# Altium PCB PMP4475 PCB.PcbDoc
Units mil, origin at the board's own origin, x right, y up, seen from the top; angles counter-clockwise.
Board outline 6000 x 4000 mil, 2 copper layers (Top Layer, Bottom Layer); 67 components, 35 nets, 172 pads, 89 vias.
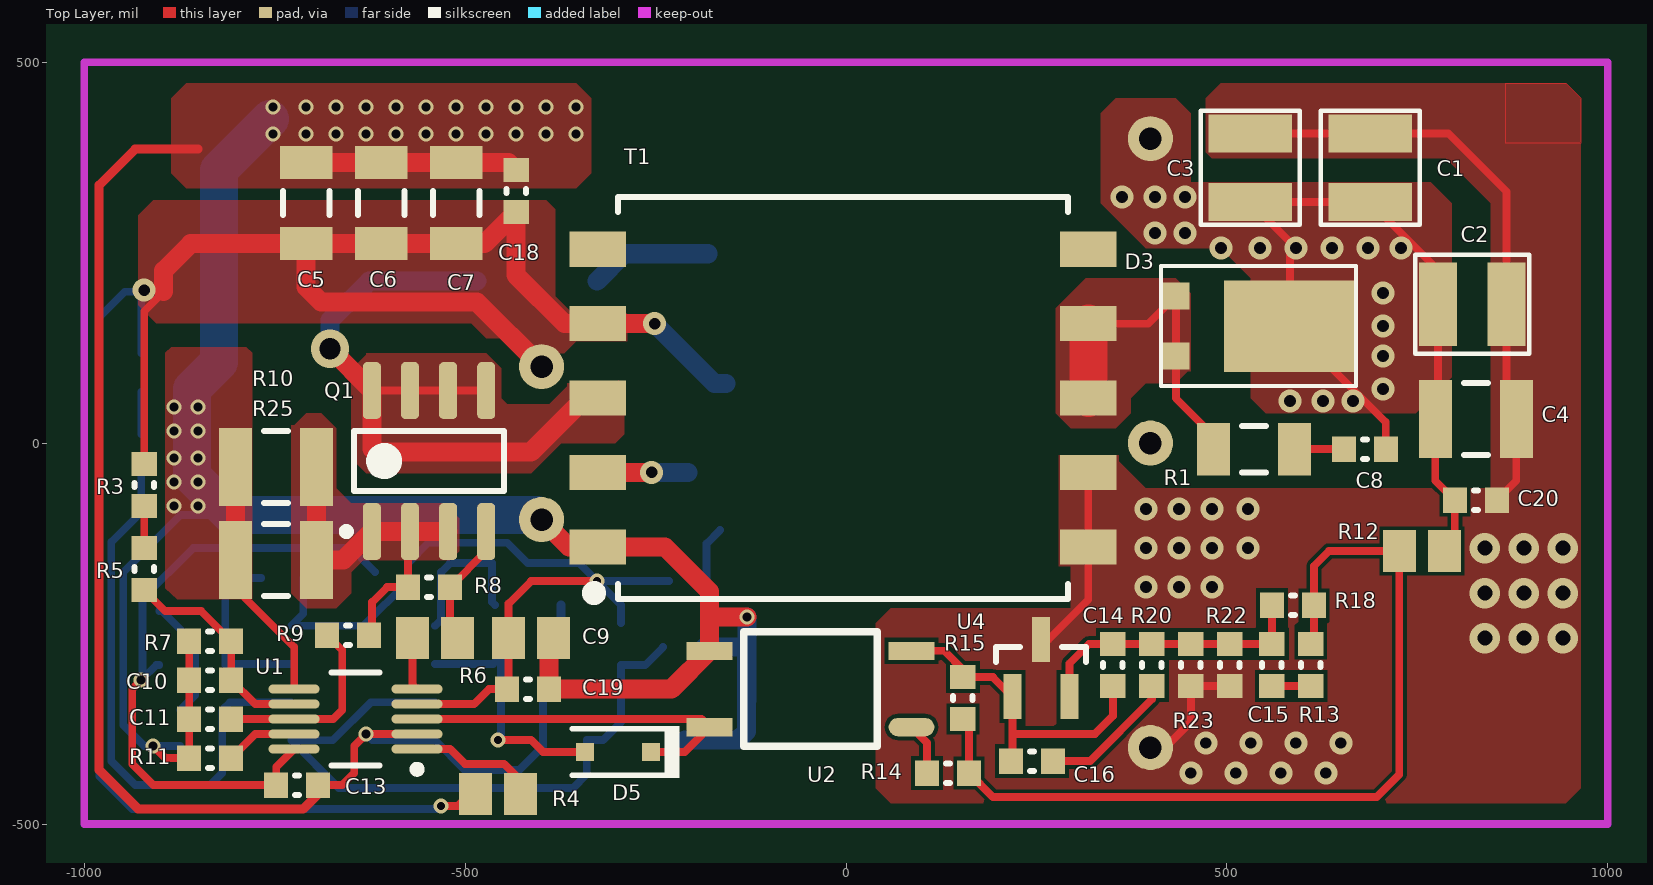
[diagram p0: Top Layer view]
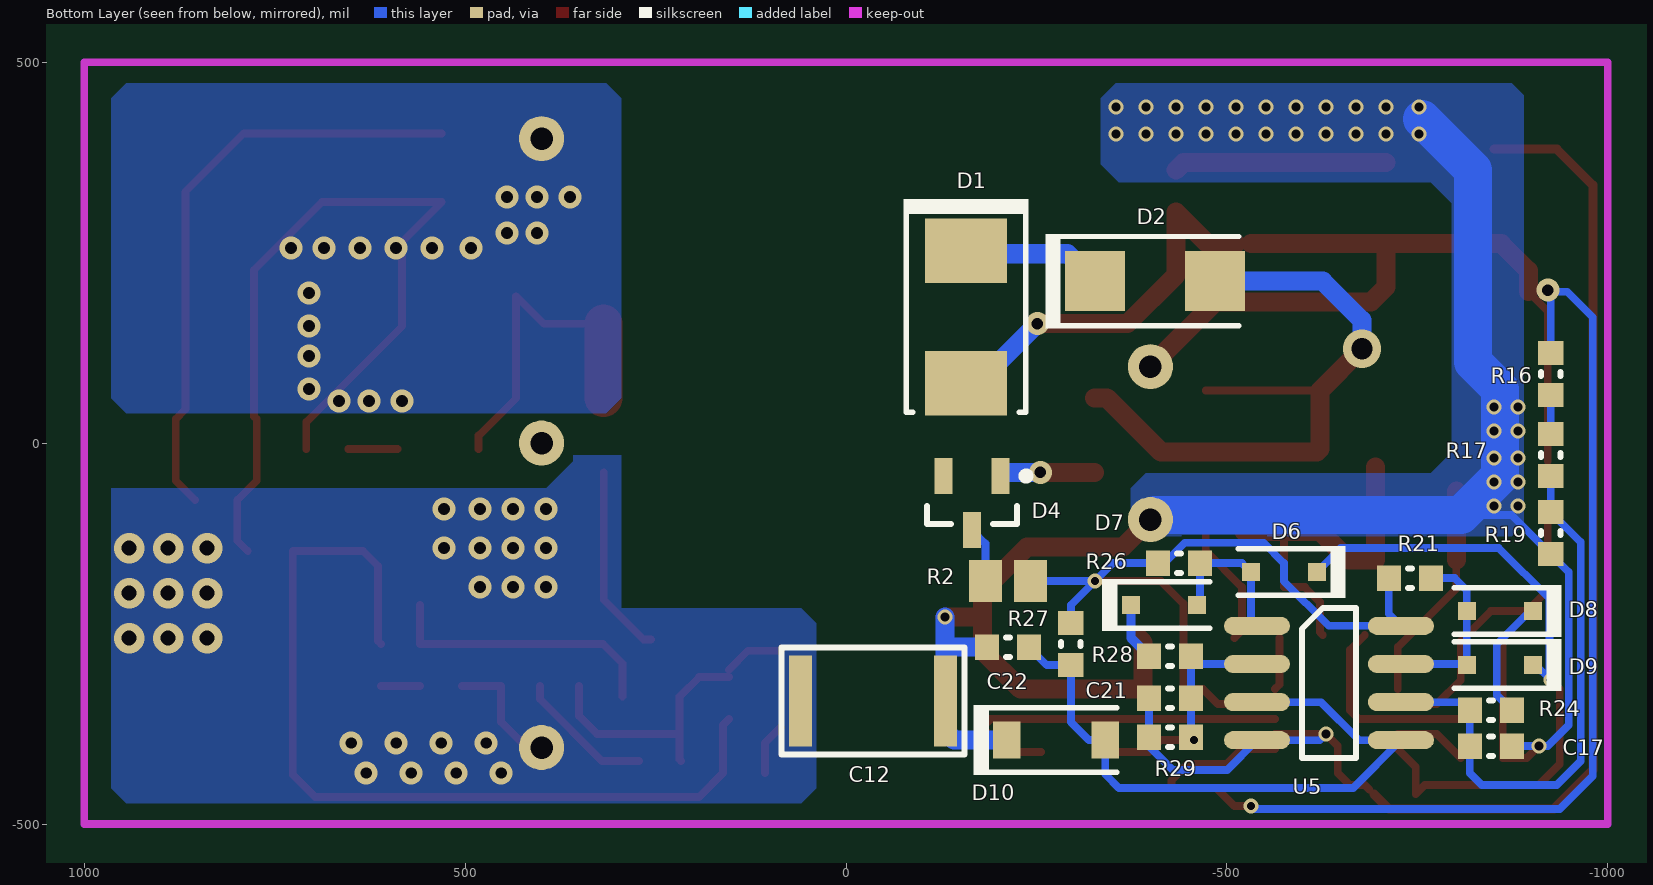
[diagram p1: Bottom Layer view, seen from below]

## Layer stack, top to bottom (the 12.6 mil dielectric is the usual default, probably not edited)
Top Layer: signal copper 1.4
Dielectric: dielectric 12.6, FR-4, Dk 4.8
Bottom Layer: signal copper 1.4

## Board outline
-2900,-2325 3100,-2325 3100,1675 -2900,1675

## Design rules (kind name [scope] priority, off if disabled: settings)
Clearance [All] p1: gap=5
MinimumSolderMaskSliver [All] p1: minsoldermaskwidth=0
PolygonConnect [All] p1: connectstyle=Direct reliefconductorwidth=10 reliefentries=4 polygonreliefangle="90 Angle" airgapwidth=10
RoutingVias [All] p1: holewidth=20 width=40 viastyle="Through Hole" minholewidth=10 minwidth=20 maxholewidth=30 maxwidth=60
SilkToSilkClearance [All] p1: silktosilkclearance=1
SilkscreenOverComponentPads [All] p1: minsilkscreentomaskgap=0
SolderMaskExpansion [All] p1: expansion=4
Width [All] p1: maxlimit=50 minlimit=10 preferedwidth=10
25 further rules are at their usual default settings.

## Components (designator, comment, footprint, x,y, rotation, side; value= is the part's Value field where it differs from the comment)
C1 "6TPE150MAPB" "POSCAP B2E Size" 748.03,291.34 r90 top
C2 "6TPE150MAPB" "POSCAP B2E Size" 751.97,122.05 r0 top
C3 "6TPE150MAPB" "POSCAP B2E Size" 590.55,291.34 r90 top
C4 "GRM32ER61A476KE20L" 1210L 826.77,31.5 r0 top
C5 "GRM31CR71H475KA12L" 1206L -708.66,314.96 r90 top
C6 "GRM31CR71H475KA12L" 1206L -610.24,314.96 r90 top
C7 "GRM31CR71H475KA12L" 1206L -511.81,314.96 r90 top
C8 "GRM1885C1H102JA01D" 0603L 681.1,-7.87 r180 top
C9 "GRM21BR71E335KA73L" 0805L -413.39,-255.91 r0 top
C10 "GRM188R71E474KA12D" 0603L -834.65,-311.02 r180 top
C11 "C0603C101J5GAC" 0603L -834.65,-362.2 r180 top
C12 "GRM1885C1H102JA01D" 2211 -35.43,-338.58 r180 bottom
C13 "GRM188R71C104KA01D" 0603L -720.47,-448.82 r0 top
C14 "GRM1885C1H102JA01D" 0603L 350.39,-291.34 r270 top
C15 "GRM188R71E474KA12D" 0603L 559.06,-291.34 r270 top
C16 "GRM188R71E474KA12D" 0603L 244.09,-417.32 r0 top
C17 "GRM188R71C104KA01D" 0603L -846.46,-397.64 r180 bottom
C18 "GRM188R71C104KA01D" 0603L -433.07,330.71 r90 top
C19 "GRM188R71C104KA01D" 0603L -417.32,-322.83 r0 top
C20 "GRM188R71C104KA01D" 0603L 826.77,-74.8 r0 top
C21 "GRM188R71C104KA01D" 0603L -425.2,-334.65 r0 bottom
C22 "GRM188R71C104KA01D" 0603L -212.6,-267.72 r0 bottom
D1 "SMBJ36A-13-F" SMB -157.48,165.35 r270 bottom
D2 "MURA160T3G" SMA -405.51,212.6 r180 bottom
D3 "PDS1040L" POWERDI-5 669.29,232.28 r180 top
D4 "BAS16-7-F" SOT-23L -165.35,-78.74 r270 bottom
D5 "BAS16" SOD-323F -299.21,-405.51 r180 top
D6 "BAS16" SOD-323F -574.8,-169.29 r0 bottom
D7 "BAS16" SOD-323F -417.32,-212.6 r180 bottom
D8 "BAS16" SOD-323F -858.27,-220.47 r0 bottom
D9 "BAS16" SOD-323F -858.27,-291.34 r0 bottom
D10 "4.3V" SOD-123 -275.59,-389.76 r180 bottom
Q1 "FDS86240" SO-8L -547.24,-23.62 r90 top
R1 "RC1206FR-0747RL" 1206L 535.43,-7.87 r0 top
R2 "CRCW080510R0FKEA" 0805L -212.6,-181.1 r180 bottom
R3 "RC0603FR-07120KL" 0603L -921.26,-55.12 r90 top
R4 "CRCW080510R0FKEA" 0805L -456.69,-460.63 r180 top
R5 "RC0603FR-0730KL" 0603L -921.26,-165.35 r90 top
R6 "RC0805FR-072R2L" 0805L -539.37,-255.91 r180 top
R7 "CRCW060310K0FKEA" 0603L -834.65,-259.84 r0 top
R8 "RT0603DRE07100KL" 0603L -547.24,-188.98 r180 top
R9 "RC0603JR-071KL" 0603L -653.54,-251.97 r180 top
R10 "RC0805FR-072R2L" 1210L -748.03,-31.5 r180 top
R11 "RC0603FR-0727KL" 0603L -834.65,-413.39 r0 top
R12 "CRCW080549R9FKEA" 0805L 755.91,-141.73 r180 top
R13 "RC0603FR-072K2L" 0603L 610.24,-291.34 r90 top
R14 "RC0603FR-071K2L" 0603L 133.86,-433.07 r0 top
R15 "RC0603FR-071K2L" 0603L 153.54,-334.65 r270 top
R16 "RC0603FR-07120KL" 0603L -925.2,90.55 r90 bottom
R17 "RC0603FR-07120KL" 0603L -925.2,-15.75 r90 bottom
R18 "CRCW060310K0FKEA" 0603L 586.61,-212.6 r0 top
R19 "RC0603FR-07120KL" 0603L -925.2,-118.11 r90 bottom
R20 "RC0603FR-071KL" 0603L 401.57,-291.34 r270 top
R21 "10k" 0603L -740.16,-177.17 r0 bottom
R22 "RC0603FR-076K2L" 0603L 503.94,-291.34 r90 top
R23 "RC0603FR-07240KL" 0603L 452.76,-291.34 r90 top
R24 "RC0603FR-07120KL" 0603L -846.46,-350.39 r0 bottom
R25 "RC0805FR-072R2L" 1210L -748.03,-153.54 r180 top
R26 "10k" 0603L -437.01,-157.48 r0 bottom
R27 "RC0603FR-07120KL" 0603L -295.28,-263.78 r90 bottom
R28 "RC0603FR-07120KL" 0603L -425.2,-279.53 r180 bottom
R29 "RC0603FR-07120KL" 0603L -425.2,-385.83 r180 bottom
T1 "Transformer" WURTH_750313995 -3.94,59.06 r90 top
U1 "LM5020MMX-1" PCBComponent_1 -562.99,-401.57 r180 top
U2 "TLP181" TLP181 125.98,-322.83 r180 top
U4 "TL431ACDBZR" DBZ0003A_N 255.91,-295.28 r90 top
U5 "LM2903" D0008A_N -633.86,-314.96 r180 bottom

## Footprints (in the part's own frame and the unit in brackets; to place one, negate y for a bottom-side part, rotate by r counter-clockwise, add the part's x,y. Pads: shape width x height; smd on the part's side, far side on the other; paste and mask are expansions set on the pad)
0603L [mm] "0603 from SM-752 data"
  rect 0.8x0.85 smd: 1(-0.7,0) 2(0.7,0)
  silkscreen extent -0.07,-0.33 0.07,0.33, body extent -0.87,-0.47 0.87,0.47, height 0.85
0805L [mm] "0805 from SM-752 data"
  rect 1.1x1.4 smd: 1(-0.75,0) 2(0.75,0)
  body extent -1.1,-0.72 1.1,0.72, height 1.1
1206L [mm] "1206 from SM-752 data"
  rect 1.1x1.75 smd: 1(-1.35,0) 2(1.35,0)
  silkscreen extent -0.4,-0.77 0.4,0.77, body extent -1.7,-0.9 1.7,0.9, height 1.35
1210L [mm] "1210 from SM-752 data"
  rect 1.1x2.6 smd: 1(-1.35,0) 2(1.35,0)
  silkscreen extent -0.4,-1.2 0.4,1.2, body extent -1.7,-1.35 1.7,1.35, height 1.35
2211 [mil] "2211size : UL1414 Class X1/Y2 recognized type"
  rect 30x120 smd: 1(-95,0) 2(95,0)
  silkscreen extent -120,-70 120,70
D0008A_N [mm] "SOIC, 8-Leads, Body 4.9x3.9mm, Pitch 1.27mm, IPC Medium Density"
  oval 2.2x0.6 smd: 1(-2.4,1.905) 2(-2.4,0.635) 3(-2.4,-0.635) 4(-2.4,-1.905) 5(2.4,-1.905) 6(2.4,-0.635) 7(2.4,0.635) 8(2.4,1.905)
  silkscreen extent -0.9,-2.5 0.9,2.5, body extent -3,-2.45 3,2.45, height 1.63
DBZ0003A_N [mm] "SOT23, 3-Leads, Body 2.9x1.3mm, Pitch 0.95mm, Lead Span 2.4mm, IPC Medium Density"
  rect 1.5x0.6 smd: 1(-0.95,0.95) 2(-0.95,-0.95) 3(0.95,0)
  silkscreen extent 0.2,-1.5 0.7,1.5, body extent -1.26,-1.46 1.26,1.46, height 0.96
PCBComponent_1 [mm]
  oval 1.7x0.3 smd: 1(0,0) 2(0,-0.5) 3(0,-1) 4(0,-1.5) 5(0,-2) 6(4.1,-2) 7(4.1,-1.5) 8(4.1,-1) 9(4.1,-0.5) 10(4.1,0)
  silkscreen extent -0.13,-2.55 2.85,0.8, body extent 0.5,-2.55 3.6,0.55, height 1.1
"POSCAP B2E Size" [mil] "B2E size (3.5 x 2.8 x 1.9mm)"
  rect 50x110 smd: 1(25,60) 2(115,60)
  silkscreen extent -5,-5 145,125
POWERDI-5 [mm]
  rect 0.9x0.9 smd: 1(6,3) 2(6,1)
  rect 4.4x3.05 smd: 3(2.2,2)
  silkscreen extent 0,0 6.5,4
SMA [mm] "Molded Diode, 2-Leads, Body 4.3x2.6mm, IPC Medium Density, based on OnSemi component dimensions and land pattern"
  rect 2x2 smd: 1(-2,0) 2(2,0)
  silkscreen extent -3.66,-1.57 2.79,1.58, body extent -2.6,-1.3 2.6,1.3, height 2.42
SMB [mil] "Molded Diode, 2-Leads, Body 5.4x3.6mm, IPC Medium Density, based on OnSemi component dimensions"
  rect 85x107.99 smd: 1(-87.01,0) 2(87.01,0)
  silkscreen extent -155,-82 125,82, body extent -106,-71 106,71, height 91
SO-8L [mm] "SOIC, 8-Leads, Body 5.0x4.0mm (max), Pitch 1.27mm, IPC Most Density"
  rrect50% 1.9x0.6 smd: 1(-2.35,1.905) 2(-2.35,0.635) 3(-2.35,-0.635) 4(-2.35,-1.905) 5(2.35,-1.905) 6(2.35,-0.635) 7(2.35,0.635) 8(2.35,1.905)
  silkscreen extent -2.47,-2.5 1,2.88, body extent -3,-2.45 3,2.45, height 1.59
SOD-123 [mm] "On Semi recommended land pattern"
  rect 0.915x1.22 smd: 1(-1.637,0) 2(1.637,0)
  silkscreen extent -2.74,-1.17 2.03,1.17, body extent -1.93,-0.9 1.93,0.9, height 1.35
SOD-323F [mm] "NXP recommended land pattern"
  rect 0.6x0.6 smd paste-0.05: 1(-1.1,0) 2(1.1,0)
  silkscreen extent -2.06,-0.86 1.53,0.86, body extent -1.35,-0.67 1.35,0.68, height 0.79
SOT-23L [mm] "SOT23, 3-Leads, Body 2.9x1.3mm, Pitch 0.95mm, Lead Span 2.5mm, IPC High Density"
  rect 1.2x0.6 smd: 1(-0.9,0.95) 2(-0.9,-0.95) 3(0.9,0)
  silkscreen extent -1.02,-1.5 0.7,1.92, body extent -1.16,-1.45 1.21,1.45, height 1
TLP181 [mil] "TOSHIBA Photocoupler GaAs Ired, Photo-Transistor"
  oval 60x24 smd: 1(40,50)
  rect 60x24 smd: 2(40,-50) 3(305,-50) 4(305,50)
  silkscreen extent 85,-75 260,75
WURTH_750313995 [mm] "WURTH"
  rect 1.17x1.88 smd: 1(-4.96,8.18) 2(-2.48,8.18) 3(0,8.18) 4(2.48,8.18) 5(4.96,8.18) 6(4.96,-8.18) 7(2.48,-8.18) 8(0,-8.18) 9(-2.48,-8.18) 10(-4.96,-8.18)
  silkscreen extent -6.7,-7.5 6.7,8.5, body extent -6.73,-8.9 6.73,8.9, height 12.7

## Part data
C1 C2 C3: library part APXA6R3ARA151MH70G, "CAP, AL, 150uF, 6.3V, +/-20%, 0.025 ohm, SMD"
C4: "CAP, CERM, 47uF, 10V, +/-10%, X5R, 1210"
C5 C6 C7: "CAP, CERM, 4.7uF, 50V, +/-10%, X7R, 1206"
C8 C12 C14: "CAP, CERM, 1000pF, 50V, +/-5%, C0G/NP0, 0603"
C9: "CAP, CERM, 3.3uF, 25V, +/-10%, X7R, 0805"
C10 C15 C16: "CAP, CERM, 0.47uF, 25V, +/-10%, X7R, 0603"
C11: "CAP, CERM, 100pF, 50V, +/-5%, C0G/NP0, 0603"
C13 C17 C18 C19 C20 C21 C22: "CAP, CERM, 0.1uF, 16V, +/-10%, X7R, 0603"
D1: "Diode, TVS, Uni, 36V, 600W, SMB"
D2: "Diode, Ultrafast, 600V, 1A, SMA"
D3: library part Diode
D4: "Diode, Ultrafast, 75V, 0.3A, SOT-23"
D5 D6 D7 D8 D9: library part Diode, "Default Diode"
D10: library part "D Zener", "Zener Diode"
Q1: library part N-MOSFET
R1: "RES, 47.0 ohm, 1%, 0.25W, 1206"
R2 R4: "RES, 10.0 ohm, 1%, 0.125W, 0805"
R3: "RES, 120k ohm, 1%, 0.1W, 0603"
R5: "RES, 30.0k ohm, 1%, 0.1W, 0603"
R6 R10 R25: "RES, 2.20 ohm, 1%, 0.125W, 0805"
R7 R18: "RES, 10.0k ohm, 1%, 0.1W, 0603"
R8: "RES, 100k ohm, 0.5%, 0.1W, 0603"
R9: "RES, 1.0k ohm, 5%, 0.1W, 0603"
R11: "RES, 27.0k ohm, 1%, 0.1W, 0603"
R12: "RES, 49.9 ohm, 1%, 0.125W, 0805"
R13: "RES, 2.20k ohm, 1%, 0.1W, 0603"
R14 R15: "RES, 1.20k ohm, 1%, 0.1W, 0603"
R16 R17 R19 R24 R27 R28 R29: "RES, 10k ohm, 1%, 0.1W, 0603"
R20: "RES, 1.00k ohm, 1%, 0.1W, 0603"
R21 R26: library part RC0603FR-07120KL, "RES, 10k ohm, 1%, 0.1W, 0603"
R22: "RES, 6.20k ohm, 1%, 0.1W, 0603"
R23: "RES, 240k ohm, 1%, 0.1W, 0603"
U1: "100V Current Mode PWM Controller, 10-pin MSOP"
U2: library part PS2811-1-M-A, "Low Input Current, Hight CTR Photocoupler"
U4: "Adjustable Precision Shunt Regulator, 34 ppm / degC, 100 mA, 0 to 70 degC, 3-pin SOT-23 (DBZ), Green (RoHS & no Sb/Br)"
U5: library part TL082ACD, "JFET-Input Operational Amplifier, 7 to 36 V, 0 to 70 degC, 8-pin SOIC (D0008A), Green (RoHS & no Sb/Br)"

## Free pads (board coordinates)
  round 59.06 hole 29.53: 1(-399.61,-100.39) 2(-399.61,100.39) 3(399.61,399.61) 4(399.61,0) 5(399.61,-399.61)

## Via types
v1: diameter 20/20 (per signal layer), hole 12, Top Layer to Bottom Layer, 33 vias
v2: diameter 30/30 (per signal layer), hole 16, Top Layer to Bottom Layer, 29 vias
v3: diameter 30, hole 15, Top Layer to Bottom Layer, 11 vias
v4: diameter 40, hole 20, Top Layer to Bottom Layer, 9 vias
v5: diameter 20, hole 12, Top Layer to Bottom Layer, 3 vias
v6: diameter 20, hole 10, Top Layer to Bottom Layer, 2 vias
v7: diameter 20/20 (per signal layer), hole 10, Top Layer to Bottom Layer, 1 vias
v8: diameter 50, hole 28, Top Layer to Bottom Layer, 1 vias

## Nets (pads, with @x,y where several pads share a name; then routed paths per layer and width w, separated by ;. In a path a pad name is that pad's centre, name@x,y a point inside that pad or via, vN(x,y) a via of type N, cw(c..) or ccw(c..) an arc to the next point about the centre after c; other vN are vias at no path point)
+VIN: C5.1 C6.1 C7.1 C18.1 D1.2 pad.2 R3.2 R4.2 R16.2 T1.4 | length 2851.2
  Top Layer w10: R3.2@-921.26,-23.62 -921.26,173.23 -895.67,198.82 ; v6(-531.5,-476.38) -509.84,-476.38 R4.2@-486.22,-452.76
  Top Layer w25: -895.67,198.82 -895.67,226.38 -860.24,261.81 C5.1 ; C7.1@-531.5,261.81 C6.1 C5.1 ; C7.1 -474.41,261.81 C18.1 -433.07,220.47 -369.29,156.69 T1.4 v3(-251.18,156.69) ; pad.2 -484.25,185.04 -688.98,185.04 -708.66,204.72 C5.1
  Bottom Layer w10: R16.2 -925.2,188.98 -915.35,198.82 -946.85,198.82 -980.32,165.35 -980.32,-437.01 -937.01,-480.32 -535.43,-480.32 v6(-531.5,-476.38)
  Bottom Layer w25: v3(-251.18,156.69) -172.83,78.35 D1.2
  other v3: -921.26,200.79
+VOUT: C1.1 C2.1 C3.1 C4.1 C8.1 C20.1 D3.3 pad.3 R12.1 | length 1115.3
  Top Layer w10: C8.1 708.66,27.56 D3.3 582.68,264.21 C3.1 C1.1 776.97,227.4 C2.1 776.97,34.84 C4.1 ; C4.1@773.62,7.87 C4.1 ; R12.1 799.21,-127.95 C20.1 773.62,-49.21 C4.1
  Bottom Layer w10: pad.3@399.61,375.98 pad.3
  other v2: 582.68,55.12 625.98,55.12 665.35,55.12 704.72,70.87 704.72,114.17 704.72,153.54 704.72,196.85 492.13,255.91 543.31,255.91 590.55,255.91 637.8,255.91 685.04,255.91 728.35,255.91 405.51,275.59 444.88,275.59 362.2,322.83 405.51,322.83 444.88,322.83
-VIN: C5.2 C6.2 C7.2 C9.2 C10.2 C11.2 C12.2 C13.2 C17.2 C18.2 C19.2 C21.2 C22.2 D10.1 pad.1 R7.1 R10.2 R11.1 R19.1 R25.2 R29.1 T1.1 U1.2 U1.6 U2.3 U5.4 | length 5017.1
  Top Layer w10: v1(-909.45,-397.64) -893.7,-413.39 R11.1 C11.2 C10.2 R7.1 ; R25.2 -801.18,-190.94 -724.41,-267.72 U1.6 ; C13.2@-687.01,-454.72 -681.1,-448.82 -661.42,-448.82 -645.67,-433.07 -645.67,-397.64 v5(-629.92,-381.89) U1.2
  Top Layer w12: -850.39,385.83 -933.07,385.83 -980.32,338.58 -980.32,-429.13 -929.13,-480.32 -712.6,-480.32 C13.2@-692.91,-460.63
  Top Layer w25: R25.2 R10.2@-801.18,-62.99 ; C5.2 C6.2 C7.2 -442.91,368.11 C18.2 ; pad.1 -363.78,-136.22 T1.1 -237.8,-136.22 -179.02,-195 -179.02,-228.35 ; C9.2 -389.76,-261.81 C19.2 -229.02,-322.83 U2.3 -179.02,-228.35 ; v5(-129.92,-228.35) -179.02,-228.35
  Bottom Layer w10: C17.2 v1(-909.45,-397.64) -921.26,-397.64 -948.82,-370.08 -948.82,-169.29 R19.1 -874.02,-94.49 -807.09,-94.49 ; v5(-629.92,-381.89) -621.85,-389.96 U5.4 -500.2,-429.13 -429.13,-429.13 -397.64,-397.64 R29.1 C21.2
  Bottom Layer w25: D10.1 -141.73,-389.76 -130.43,-378.46 C12.2 ; C22.2 -130.43,-267.72 C12.2 ; v5(-129.92,-228.35) -129.92,-338.07 C12.2
  Bottom Layer w50: -755.91,425.2 -822.83,358.27 -822.83,106.3 -858.27,70.87 -858.27,-43.31 -807.09,-94.49 -405.51,-94.49 pad.1
  other v1: -881.89,-82.68 -850.39,-82.68 -881.89,-51.18 -850.39,-51.18 -881.89,-19.68 -850.39,-19.68 -881.89,15.75 -850.39,15.75 -881.89,47.24 -850.39,47.24 -751.97,405.51 -708.66,405.51 -669.29,405.51 -629.92,405.51 -590.55,405.51 -551.18,405.51 -511.81,405.51 -472.44,405.51 -433.07,405.51 -393.7,405.51 -354.33,405.51 -751.97,440.94 -708.66,440.94 -669.29,440.94 -629.92,440.94 -590.55,440.94 -551.18,440.94 -511.81,440.94 -472.44,440.94 -433.07,440.94 -393.7,440.94 -354.33,440.94
-VOUT: C1.2 C2.2 C3.2 C4.2 C12.1 C20.2 pad.5 R22.1 R23.1 T1.9 T1.10 U4.3 | length 1205
  Top Layer w10: U4.3 265.75,-257.87 318.11,-205.51 T1.10 T1.9 ; pad.5 419.29,-399.61 452.76,-366.14 R23.1 R22.1 ; C3.2 C1.2 790.51,406.34 866.97,329.88 C2.2 866.97,44.45 C4.2 879.92,-49.21 C20.2
  other v2: 393.7,-188.98 437.01,-188.98 480.31,-188.98 393.7,-137.8 437.01,-137.8 480.31,-137.8 527.56,-137.8 393.7,-86.61 437.01,-86.61 480.31,-86.61 527.56,-86.61
  other v3: 452.76,-433.07 511.81,-433.07 570.87,-433.07 629.92,-433.07 472.44,-393.7 531.5,-393.7 590.55,-393.7 649.61,-393.7
  other v4: 838.58,-255.91 889.76,-255.91 940.94,-255.91 838.58,-196.85 889.76,-196.85 940.94,-196.85 838.58,-137.8 889.76,-137.8 940.94,-137.8
NetC8_2: C8.2 R1.2 | length 65
  Top Layer w10: R1.2 C8.2
NetC10_1: C10.1 R5.1 R7.2 U1.7 | length 257.3
  Top Layer w10: R5.1 -893.7,-220.47 -846.46,-220.47 R7.2 C10.1 -775.59,-342.52 U1.7@-755.91,-342.52
NetC11_1: C11.1 R9.2 U1.8 | length 257.1
  Top Layer w10: C11.1 U1.8 -673.23,-362.2 -661.42,-350.39 -661.42,-271.65 R9.2
NetC14_1: C14.1 C15.1 R18.1 R20.1 R22.2 R23.2 U4.2 | length 370.8
  Top Layer w10: U4.2 293.31,-289.37 318.9,-263.78 C14.1 R20.1 R23.2 R22.2 C15.1 R18.1
NetC14_2: C14.2 C16.1 R15.1 U2.2 U4.1 | length 419.9
  Top Layer w10: U2.2 128.74,-272.83 R15.1@153.54,-297.64 ; R15.1 192.91,-307.09 U4.1 218.5,-381.89 ; C16.1 218.5,-415.35 218.5,-381.89 ; C14.2 350.39,-358.27 326.77,-381.89 218.5,-381.89
NetC15_2: C15.2 R13.1 | length 51.2
  Top Layer w10: C15.2 R13.1
NetC16_2: C16.2 R20.2 | length 180.8
  Top Layer w10: C16.2 320.43,-417.32 401.57,-336.17 R20.2
NetC17_1: C17.1 R17.1 R19.2 R24.2 U5.6 | length 733.1
  Bottom Layer w10: R17.1 R19.2 -964.57,-129.92 -964.57,-417.32 -933.07,-448.82 -834.65,-448.82 -818.9,-433.07 C17.1 R24.2 -808.46,-339.96 U5.6
NetC21_1: C21.1 D5.2 R28.2 R29.2 U5.2 | length 317.9
  Top Layer w10: v7(-456.69,-389.76) -413.39,-389.76 -397.64,-405.51 D5.2
  Bottom Layer w10: U5.2 -463.19,-289.96 R28.2 C21.1 R29.2
NetC22_1: C22.1 D10.2 R27.1 U5.3 U5.5 | length 870.6
  Bottom Layer w10: U5.3 -623.43,-339.96 -673.43,-389.96 U5.5 -665.55,-452.76 -358.27,-452.76 -340.06,-434.55 D10.2 -318.9,-389.76 -295.28,-366.14 R27.1 -263.78,-291.34 C22.1
NetD1_1: D1.1 D2.1 | length 160.5
  Bottom Layer w25: D2.1 -290.94,248.43 D1.1@-181.1,248.43
NetD2_2: D2.2 Q1.5 Q1.6 Q1.7 Q1.8 T1.3 | length 883.3
  Top Layer w10: Q1.8 Q1.7 Q1.6 Q1.5
  Top Layer w25: v8(-677.17,123.82) Q1.8 -622.24,-7.68 -618.11,-11.81 -413.39,-11.81 -342.52,59.06 T1.3
  Bottom Layer w25: v8(-677.17,123.82) -677.17,161.42 -625.98,212.6 D2.2
NetD3_1: D3.1 D3.2 R1.1 T1.7 T1.8 | length 448.8
  Top Layer w10: T1.7 396.85,156.69 D3.2 D3.1 433.07,59.06 482.28,9.84 R1.1
  Top Layer w50: T1.8 T1.7
NetD4_1: D4.1 T1.2 | length 118.5
  Top Layer w25: T1.2 v3(-255.12,-38.58)
  Bottom Layer w25: v3(-255.12,-38.58) D4.1@-207.48,-38.58
NetD4_3: D4.3 R2.1 | length 74.3
  Bottom Layer w10: R2.1 -183.07,-131.89 D4.3
NetD5_1: D5.1 U1.3 U2.4 | length 478.8
  Top Layer w10: U1.3 -189.65,-362.2 U2.4 -211.69,-405.51 D5.1
NetD6_2: D6.2 D7.2 R26.1 U5.1 | length 202.5
  Bottom Layer w10: U5.1 -531.5,-232.09 D6.2 -519.68,-157.48 R26.1 -464.57,-208.66 D7.2
NetD7_1: D7.1 R28.1 | length 76.7
  Bottom Layer w12: R28.1 -374.02,-255.91 D7.1
NetD8_1: D8.1 R24.1 | length 160
  Bottom Layer w10: D8.1 -897.64,-220.47 -854.33,-263.78 -854.33,-330.71 R24.1
NetD8_2: D8.2 D9.2 R21.1 U5.7 | length 239.4
  Bottom Layer w10: R21.1 -799.21,-177.17 -814.96,-192.91 D8.2 D9.2 -813.58,-289.96 U5.7
NetQ1_1: Q1.1 Q1.2 Q1.3 R8.2 R9.1 R10.1 R25.1 | length 484.4
  Top Layer w10: R9.1 -622.05,-248.03 -622.05,-208.66 -602.36,-188.98 R8.2 -574.8,-118.7 Q1.2
  Top Layer w25: R10.1 R25.1 -659.65,-153.54 Q1.1 Q1.2 Q1.3
NetQ1_4: Q1.4 R6.1 R8.1 | length 163.5
  Top Layer w10: R6.1 -519.68,-246.06 R8.1 -472.24,-141.54 Q1.4
NetR3_1: R3.1 R5.2 | length 55.1
  Top Layer w10: R5.2 R3.1
NetR4_1: R4.1 U1.1 | length 162.8
  Top Layer w10: U1.1 -519.68,-401.57 -500,-421.26 -448.82,-421.26 -427.17,-442.91 R4.1@-427.17,-452.76
NetR6_2: R6.2 U1.5 | length 69.4
  Top Layer w10: R6.2 -568.9,-316.93 U1.5
NetR11_2: R11.2 U1.9 | length 95.7
  Top Layer w10: R11.2 -775.59,-381.89 U1.9
NetR12_2: R12.2 R13.2 R14.2 R15.2 R18.2 | length 1182
  Top Layer w10: R15.2 161.42,-370.08 R14.2 192.91,-464.57 696.85,-464.57 726.38,-435.04 R12.2 633.86,-141.73 614.17,-161.42 R18.2 614.17,-259.84 R13.2
NetR14_1: R14.1 U2.1 | length 68.7
  Top Layer w10: U2.1 106.3,-393.15 R14.1
NetR16_1: R16.1 R17.2 | length 55.1
  Bottom Layer w10: R17.2 R16.1@-925.2,66.93
SS: C13.1 D6.1 D9.1 U1.10 | length 871.7
  Top Layer w10: v5(-925.2,-311.02) -937.01,-322.83 -937.01,-421.26 -909.45,-448.82 -759.84,-448.82 -748.03,-460.63 -748.03,-425.2 U1.10
  Bottom Layer w10: v5(-925.2,-311.02) v5@-923.39,-309.21 ; D9.1 -905.51,-291.34 v5@-923.39,-309.21 ; D6.1 -649.61,-137.8 -856.66,-137.8 -923.39,-204.52 v5@-923.39,-309.21
VCC: C9.1 C19.1 R2.2 R21.2 R26.2 R27.2 U1.4 U5.8 | length 1081.1
  Top Layer w10: U1.4 -488.19,-342.52 -468.5,-322.83 C19.1 -442.91,-320.87 C9.1 -442.91,-210.63 -413.39,-181.1 v6(-326.77,-181.1)
  Bottom Layer w10: R21.2 -712.6,-224.21 U5.8 -633.66,-239.96 -574.8,-181.1 -574.8,-157.48 -548.07,-130.75 -444.68,-130.75 -417.94,-157.48 R26.2 -350.39,-157.48 v6(-326.77,-181.1) ; R27.2 -295.28,-212.6 v6(-326.77,-181.1) ; R2.2@-232.28,-181.1 R2.2 v6(-326.77,-181.1)
pads on no net: D4.2 T1.5 T1.6

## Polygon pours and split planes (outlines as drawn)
+VIN on Top Layer "Bottom Layer-No Net" (solid, remove dead copper, pour order 26): -748.03,157.48 -905.51,157.48 -921.26,173.23 -929.13,181.1 -929.13,240.16 -929.13,299.21 -909.45,318.9 -393.7,318.9 -381.89,307.09 -381.89,244.09 -405.51,244.09 -492.13,157.48 -748.03,157.48
-VIN on Top Layer "Bottom Layer-No Net" (solid, remove dead copper, pour order 22): -866.14,472.44 -885.83,452.76 -885.83,354.33 -866.14,334.65 -354.33,334.65 -334.65,354.33 -334.65,452.76 -354.33,472.44 -866.14,472.44
-VIN on Top Layer "Bottom Layer-No Net" (solid, remove dead copper, pour order 18): -893.7,125.98 -893.7,54.09 -893.7,-190.35 -885.83,-197.54 -877.95,-204.72 -779.53,-204.72 -779.53,-125.64 -779.53,118.8 -787.4,125.98 -885.83,125.98 -893.7,118.8
-VOUT on Top Layer "Bottom Layer-No Net" (solid, remove dead copper, pour order 28): 866.14,472.44 944.88,472.44 964.57,452.76 964.57,393.7 866.14,393.7 866.14,472.44
-VOUT on Top Layer "Bottom Layer-No Net" (solid, remove dead copper, pour order 21): 59.06,-472.44 39.37,-452.76 39.37,-236.22 59.06,-216.54 275.59,-216.54 295.28,-216.54 295.28,-15.75 358.27,-15.75 358.27,-23.62 374.02,-39.37 393.7,-59.06 964.57,-59.06 964.57,-452.76 944.88,-472.44 59.06,-472.44
NetQ1_1 on Top Layer "Bottom Layer-No Net" (solid, remove dead copper, pour order 31): -708.66,-216.54 -728.35,-196.85 -728.35,3.94 -728.35,23.62 -724.41,23.62 -708.66,39.37 -688.98,39.37 -669.29,19.68 -669.29,-78.74 -669.29,-59.06 -649.61,-78.74 -527.56,-78.74 -507.87,-98.43 -507.87,-141.73 -519.68,-153.54 -633.86,-153.54 -649.61,-169.29 -649.61,-196.85 -669.29,-216.54 -708.66,-216.54
NetD2_2 on Top Layer "Bottom Layer-No Net" (solid, remove dead copper, pour order 30): -472.44,-39.37 -629.92,-39.37 -649.61,-19.69 -649.61,-19.68 -649.61,96.26 -649.7,96.36 -629.92,116.14 -629.92,118.11 -472.44,118.11 -452.76,98.43 -452.76,59.06 -444.88,51.18 -433.07,51.18 -389.76,51.18 -366.14,74.8 -366.14,78.74 -303.15,78.74 -299.21,82.68 -291.34,74.8 -291.34,47.24 -291.34,11.81 -303.15,0 -374.02,0 -413.39,-39.37 -472.44,-39.37
+VIN on Top Layer "Bottom Layer-No Net" (solid, remove dead copper, pour order 29): -767.72,177.17 -748.03,157.48 -492.13,157.48 -472.44,137.8 -452.76,137.8 -433.07,118.11 -370.08,118.11 -354.33,133.86 -287.4,133.86 -287.4,169.29 -291.34,173.23 -362.2,173.23 -381.89,192.91 -381.89,244.09 -381.89,255.91 -405.51,279.53 -767.72,279.53 -771.65,279.53 -791.34,259.84 -787.4,255.91 -787.4,196.85 -748.03,157.48
-VOUT on Top Layer "Bottom Layer-No Net" (solid, remove dead copper, pour order 27): 964.57,-82.68 964.57,452.76 944.88,472.44 492.13,472.44 472.44,452.76 472.44,393.7 472.44,381.89 480.31,374.02 787.4,374.02 846.46,314.96 846.46,-23.62 846.46,-82.68 870.08,-106.3 893.7,-106.3 956.69,-106.3 960.63,-102.36 964.57,-98.43 964.57,-82.68
-VOUT on Top Layer "Bottom Layer-No Net" (solid, remove dead copper, pour order 26): 279.53,-15.75 279.53,-161.42 354.33,-161.42 358.27,-157.48 358.27,-15.75 279.53,-15.75
-VOUT on Top Layer "Bottom Layer-No Net" (solid, remove dead copper, pour order 20): 472.44,433.07 492.13,452.76 846.46,452.76 925.2,374.02 925.2,-19.68 905.51,-39.37 866.14,-39.37 850.39,-23.62 846.46,-23.62 846.46,275.59 846.46,314.96 787.4,374.02 492.13,374.02 472.44,393.7 472.44,433.07
+VOUT on Top Layer "Bottom Layer-No Net" (solid, remove dead copper, pour order 19): 354.33,452.76 334.65,433.07 334.65,314.96 374.02,275.59 393.7,255.91 413.39,255.91 413.39,283.46 452.76,322.83 452.76,433.07 433.07,452.76 354.33,452.76
NetD3_1 on Top Layer "Bottom Layer-No Net" (solid, remove dead copper, pour order 18): 295.28,196.85 275.59,177.17 275.59,39.37 295.28,19.69 295.28,19.68 354.33,19.68 374.02,39.37 374.02,59.06 393.7,78.74 433.07,78.74 448.82,94.49 452.76,94.49 452.76,196.85 433.07,216.54 314.96,216.54 295.28,196.85 291.34,196.85
+VOUT on Top Layer "Bottom Layer-No Net" (solid, remove dead copper, pour order 17): 452.76,255.91 492.13,255.91 531.5,216.54 531.5,59.06 551.18,39.37 748.03,39.37 795.28,86.61 795.28,314.96 767.72,342.52 763.78,342.52 413.39,342.52 393.7,322.83 393.7,275.59 413.39,255.91 448.82,255.91
-VIN on Bottom Layer "Bottom Layer-No Net" (solid, remove dead copper, pour order 30): -889.76,70.87 -889.76,291.34 -889.76,456.69 -874.02,472.44 -846.46,472.44 -846.46,468.5 -850.39,464.57 -850.39,47.24 -866.14,47.24 -889.76,70.87
-VIN on Bottom Layer "Bottom Layer-No Net" (solid, remove dead copper, pour order 28): -893.7,157.48 -893.7,-102.36 -874.02,-122.05 -696.85,-122.05 -401.57,-122.05 -377.95,-98.43 -374.02,-94.49 -374.02,-59.06 -393.7,-39.37 -748.03,-39.37 -767.72,-39.37 -795.28,-11.81 -795.28,106.3 -795.28,314.96 -771.65,338.58 -767.72,342.52 -374.02,342.52 -358.27,342.52 -334.65,366.14 -334.65,452.76 -354.33,472.44 -866.14,472.44 -885.83,452.76 -885.83,240.16 -874.02,228.35 -866.14,220.47 -866.14,133.86 -866.14,98.43 -881.89,82.68 -889.76,74.8 -889.76,70.87 -889.76,-106.3
-VOUT on Bottom Layer "Bottom Layer-No Net" (solid, remove dead copper, pour order 23): 59.06,-472.44 39.37,-452.76 39.37,-236.22 59.06,-216.54 295.28,-216.54 295.28,-15.75 358.27,-15.75 358.27,-23.62 393.7,-59.06 964.57,-59.06 964.57,-452.76 944.88,-472.44 59.06,-472.44
+VOUT on Bottom Layer "Bottom Layer-No Net" (solid, remove dead copper, pour order 24): 314.96,472.44 295.28,452.76 295.28,307.09 295.28,59.06 314.96,39.37 944.88,39.37 964.57,59.06 964.57,452.76 944.88,472.44 314.96,472.44
+VOUT on Bottom Layer "Bottom Layer-No Net" (solid, remove dead copper, pour order 22): 314.96,334.65 295.28,314.96 295.28,59.06 314.96,39.37 783.46,39.37 799.21,55.12 799.21,59.06 799.21,307.09 795.28,311.02 771.65,334.65 767.72,334.65 318.9,334.65

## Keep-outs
Keep-Out Layer:
  lines w10: -1000,-500 1000,-500 1000,500 -1000,500 -1000,-500

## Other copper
Top Layer:
  pour cut-out: 753.03,-109.17 758.78,-109.17 758.78,-174.29 753.03,-174.29
  pour cut-out: 423.31,-298.15 423.31,-284.53 328.66,-284.53 328.66,-273.98 323.12,-273.98 303.57,-293.53 305.48,-295.44 305.48,-298.15 310.12,-298.15 310.12,-371.69 322.55,-371.69 340.2,-354.04 340.2,-339.65 328.66,-339.65 328.66,-298.15 372.13,-298.15 372.13,-339.65 360.59,-339.65 360.59,-356.21 362.5,-358.12 365.21,-358.12 380.97,-342.36 379.84,-341.24 379.84,-298.15
  pour cut-out: 237.28,-439.06 250.91,-439.06 250.91,-439.05 250.91,-395.59 247.4,-392.09 240.79,-392.09 237.28,-395.59
  pour cut-out: 580.79,-329.09 588.5,-329.09 588.5,-339.65 580.79,-339.65
  pour cut-out: 580.79,-298.15 588.5,-298.15 588.5,-308.7 580.79,-308.7
  pour cut-out: 537.32,-273.98 537.32,-284.53 525.67,-284.53 525.67,-273.98
  pour cut-out: 624.37,-234.33 634.92,-234.33 631.97,-237.28 631.97,-243.03 624.37,-243.03
  pour cut-out: 593.43,-234.33 603.98,-234.33 603.98,-243.03 588.5,-243.03 588.5,-239.25
  pour cut-out: 569.25,-234.33 579.8,-234.33 579.8,-242.05 580.79,-243.03 569.25,-243.03
  pour cut-out: 525.67,-243.03 537.32,-243.03 538.31,-242.05 538.31,-234.33 548.86,-234.33 548.86,-243.03 537.32,-243.03 537.32,-253.58 525.67,-253.58
  pour cut-out: 474.49,-273.98 482.2,-273.98 482.2,-284.53 474.49,-284.53
  pour cut-out: 474.49,-243.03 474.49,-253.58 482.2,-253.58 482.2,-243.03
  pour cut-out: 379.84,-273.98 372.13,-273.98 372.13,-284.53 379.84,-284.53
  pour cut-out: 423.31,-273.98 431.02,-273.98 431.02,-284.53 423.31,-284.53
  pour cut-out: 423.31,-243.03 431.02,-243.03 431.02,-253.58 423.31,-253.58
  pour cut-out: 379.84,-243.03 379.84,-253.58 372.13,-253.58 372.13,-243.03
  pour cut-out: -796.89,-281.57 -786.34,-281.57 -786.34,-289.29 -796.89,-289.29
  pour cut-out: -827.83,-281.57 -817.28,-281.57 -817.28,-289.29 -827.83,-289.29 -827.83,-281.57
  pour cut-out: -827.83,-340.47 -798.59,-340.47 -797.12,-339 -797.12,-335.53 -799.89,-332.76 -827.83,-332.76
